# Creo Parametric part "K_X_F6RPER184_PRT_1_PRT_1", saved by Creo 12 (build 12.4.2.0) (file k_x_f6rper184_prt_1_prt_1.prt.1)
Units: Custom; MM, KILOGRAM, SECS

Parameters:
  PTC_WM_ITERATION = "0"
  PTC_WM_VERSION = "-.0"
  PTC_WM_LIFECYCLE_STATE = "In Work"
  PTC_WM_LIFECYCLE = "MO_CADDocument"
  PTC_WM_CREATED_BY = "Maximilian Roepper (Z0017RMS: MO)"
  PTC_WM_CREATED_ON = "18-Sep-26 11:36:42 AM"
  PTC_WM_MODIFIED_BY = "Maximilian Roepper (Z0017RMS: MO)"
  PTC_WM_MODIFIED_ON = "18-Sep-26 11:36:46 AM"
  PDMLINKNUMBER = "PDM000071455014"
  PTC_WM_NAME = "k_x_f6rper184_prt_1_prt_1.prt"
  PTC_WM_NUMBER = "PDM000071455014"

Other parameters: WEIGHT, WEIGHT_FACTOR, WEIGHT_ADD, _MASS_TEMP, _DIFF_TEMP, MC_ERRORS, SUPPLIER

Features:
  1. coordinate system
  2. datum plane "PRT_YZ"
  3. datum plane "PRT_XY"
  4. datum plane "PRT_XZ"
  5. coordinate system
  6. datum axis
  7. datum axis
  8. datum axis
  9. coordinate system
  10. imported feature
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
Other named items: PRT, SIEMENS_MO, DRW_VIEW_ORG, PRT_X, PRT_Y, PRT_Z, CS0, ROUGH_GROB

Layers: 00_STD_CSYS-KSYS, 01_STD_PLANES-EBENEN, 02_STD_AXES-ACHSEN, 03_STD_CSYS-KSYS, 24_IMPORT_FEAT-IMPORT_KE

Surfaces: 12 plane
